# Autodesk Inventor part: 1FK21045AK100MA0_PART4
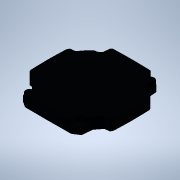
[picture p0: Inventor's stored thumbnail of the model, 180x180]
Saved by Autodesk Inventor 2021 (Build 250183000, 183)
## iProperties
Created: 2025-04
Part Number: 1FK21045AK100MA0_PART4
Material: Generic
Catalog Web Link: www.3dfindit.com
Description: -Servo synchronous motor
Document SubType Name: Modeling
Designer: psAdmin
Mass: 55.5405 g
Surface Area: 149.572 cm^2
Volume: 55.5405 cm^3
Density: 1 g/cm^3
Appearance: PSOLRGB-38-46-56
Category: PARTsolutions
Title: 1FK21045AK100MA0_PART4
Author: Cadenas PARTsolutions
Comments: Servo synchronous motor
Sending System: PARTsolutions
Preprocessor: ST-DEVELOPER v19.3
PSOL_IDENT_0: {$CADENAS_DATA/23d-libs/siemens_ag/_cat_/e0/5f/1fk21045ak100ma0.prj},213 {VTYP=3D},{NB=1FK21045AK100
PSOL_IDENT_1: MA0_PART4},{LINA=1FK21045AK100MA0_PART4},{NN=1FK21045AK100MA0_PART4},{NOPRJ=TRUE},{DATE=19.08.2025 1
PSOL_IDENT_2: 4:01:03},{GEOMDATE=30.07.2025 02:01:57},{VERSION=},{LINEID=10},{WBVAR=},{WBNUMERIC=}  {NB=1FK21045AK
PSOL_IDENT_3: 100MA0_PART4},{LINA=1FK21045AK100MA0_PART4},{KT=DUMMY},{PREVIEW=../../../_pool_/0f/2c/p_d211_xx_0043
PSOL_IDENT_4: 8j.png},{DESCSHORT=SIMOTICS S-1FK2 HD, SINAMICS S210 3AC 400V-480V, 1.7 Nm, 6000 rpm},{DESCLONG=SIMO
PSOL_IDENT_5: TICS S-1FK2 HD servo motor M0=2.4 Nm; PN = 1.07 kW at nN=6000 rpm (380-480 V); PN = 0.75 kW at nN=30
PSOL_IDENT_6: 00 rpm (200-240 V); with holding brake; degree of protection IP64; cylindrical shaft D19x40mm; absol
PSOL_IDENT_7: ute encoder 22-bit + 12-bit multiturn (encoder AM22DQC); with OCC interface; plug size M17, rotatabl
PSOL_IDENT_8: e; SIMOTICS S-1FK2 servomotorfor a wide range of uses in industrial environments. SIMOTICS S‑1FK2 se
PSOL_IDENT_9: rvomotors are compact synchronous motors with a high dynamic performance that set themselves apart a
PSOL_IDENT_10: s a result of their high power density, degree of protection and overload capability. The motors are
PSOL_IDENT_11: available in two variants: as High Dynamic variant (highest dynamic performance as a result of the
PSOL_IDENT_12: low intrinsic moment of inertia for applications demanding a high dynamic performance with low moved
PSOL_IDENT_13: masses) - and as Compact variant (precise and stable closed-loop control for medium up to large mov
PSOL_IDENT_14: ed masses as a result of a medium intrinsic moment of inertia). SIMOTICSS‑1FK2 servomotors fully exp
PSOL_IDENT_15: loit their strengths in a system with the SINAMICSS210 frequency converter and simple connection usi
PSOL_IDENT_16: ng the one cable connection (OCC). Advantages include the short control and positioning times, fast
PSOL_IDENT_17: and precise correction of disturbing quantities as well as stable control with a high dynamic perfor
PSOL_IDENT_18: mance. The servo motors can be configured to address a wide range of requirements. For example with
PSOL_IDENT_19: and without holding brake, IP64 or IP65 degree of protection, singleturn or multiturn absolute encod
PSOL_IDENT_20: ers - to name just a few. Further, the servomotors are available in different shaft heights extendin
PSOL_IDENT_21: g from 20 to 100. A shaft sealing ring is available to achieve an IP65 degree of protection and for
PSOL_IDENT_22: subsequent mounting at the motor or as spare part. SIMOTICS - the optimum motor for each and every m
PSOL_IDENT_23: otion control application.},{INTNO=804766807114},{SUPPLIERALTNO=1FK2104-5AK10-0MA0},{MANUID=1FK21045
PSOL_IDENT_24: AK100MA0},{MANUNAME=Siemens},{MANUTYPEDESC=Synchronous motor 1FK2-HD 2,39 Nm},{AAU732=SIMOTICS},{AAO
PSOL_IDENT_25: 057=S-1FK2},{AAU734=SIMOTICS S-1FK2 HD servo motor M0=2.4 Nm; PN = 1.07 kW at nN=6000 rpm (380-480 V
PSOL_IDENT_26: ); PN = 0.75 kW at nN=3000 rpm (200-240 V); with holding brake; degree of protection IP64; cylindric
PSOL_IDENT_27: al shaft D19x40mm; absolute encoder 22-bit + 12-bit multiturn (encoder AM22DQC); with OCC interface;
PSOL_IDENT_28: plug size M17, rotatable;},{AAW338=Synchronous motor 1FK2-HD 2,39 Nm},{AAO742=SIMOTICS},{AAO663=404
PSOL_IDENT_29: 2948691236},{NOCUPEROU=1},{PRICEQUANTITY=1},{QUANTITYMIN=1},{QUANTITYINT=1},{CTN=85015100},{COO=DE},
PSOL_IDENT_30: {AAO676=1FK2104-5AK10-0MA0},{AAO677=Siemens AG},{ORDERUNIT=C62},{CONTENTUNIT=C62}
NB: 1FK21045AK100MA0_PART4
NT: Servo synchronous motor
NBSYN: $MANUID._PART4
LINA: 1FK21045AK100MA0_PART4
CATALOG: SIEMENS
PREVIEW: ../../../_pool_/0f/2c/p_d211_xx_00438j.png
DESCSHORT: SIMOTICS S-1FK2 HD, SINAMICS S210 3AC 400V-480V, 1.7 Nm, 6000 rpm
DESCLONG: SIMOTICS S-1FK2 HD servo motor M0=2.4 Nm; PN = 1.07 kW at nN=6000 rpm (380-480 V); PN = 0.75 kW at nN=3000 rpm (200-240 V); with holding brake; degree of protec
INTNO: 804766807114
SUPPLIERALTNO: 1FK2104-5AK10-0MA0
MANUID: 1FK21045AK100MA0
MANUNAME: Siemens
MANUTYPEDESC: Synchronous motor 1FK2-HD 2,39 Nm
AAU732: SIMOTICS
AAO057: S-1FK2
AAU734: SIMOTICS S-1FK2 HD servo motor M0=2.4 Nm; PN = 1.07 kW at nN=6000 rpm (380-480 V); PN = 0.75 kW at nN=3000 rpm (200-240 V); with holding brake; degree of protec
AAW338: Synchronous motor 1FK2-HD 2,39 Nm
AAO742: SIMOTICS
AAO663: 4042948691236.0
NOCUPEROU: 1
PRICEQUANTITY: 1
QUANTITYMIN: 1
QUANTITYINT: 1
CTN: 85015100
COO: DE
ARTICLENO: 1FK21045AK100MA0_PART4
BOMINFO: 1FK21045AK100MA0_PART4
CREATOR: CADENAS GmbH
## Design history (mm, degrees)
feature "2025_04_17_15_45_15_0043"
body "Solid1"
